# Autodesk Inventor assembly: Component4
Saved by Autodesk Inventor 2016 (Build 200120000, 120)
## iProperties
Created: 2018-05
Part Number: Component4
Document SubType Name: Assembly
Designer: Administrator
Title: Component4
Author: Administrator
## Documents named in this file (2)
- c:\worker\convert-fusion-mar-2018\tmp\job-1\16\output\files\8c58ff39-88bb-4352-afd9-60265520bae5\Component4.iam
- c:\worker\convert-fusion-mar-2018\tmp\job-1\16\output\files\8c58ff39-88bb-4352-afd9-60265520bae5\Component5.ipt
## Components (1 placed, 1 different names)
1. Component5:1
